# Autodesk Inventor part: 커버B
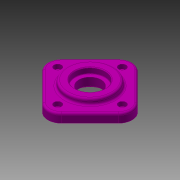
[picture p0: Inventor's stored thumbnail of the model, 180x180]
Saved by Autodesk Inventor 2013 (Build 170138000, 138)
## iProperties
Created: 2013-01
Part Number: 커버B
Document SubType Name: Modeling
Density: 1 g/cm^3
Material: 알루미늄 6061
Designer: mdu
Author: mdu
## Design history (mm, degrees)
sketch "스케치1"
  geometry: L1 (56.569, -14.142)-(14.142, -56.569) reference; L2 (-14.142, -56.569)-(-56.569, -14.142) reference; L3 (-56.569, 14.142)-(-14.142, 56.569) reference; L4 (14.142, 56.569)-(56.569, 14.142) reference; C1 r 31 at (0, 0) reference; A1 r 20 centre (0, -42.426) between (-14.142, -56.569) and (14.142, -56.569) reference; A2 r 20 centre (-42.426, 0) between (-56.569, 14.142) and (-56.569, -14.142) reference; A3 r 20 centre (0, 42.426) between (14.142, 56.569) and (-14.142, 56.569) reference; A4 r 20 centre (42.426, 0) between (56.569, -14.142) and (56.569, 14.142) reference; 1 further point
extrude "돌출1" new body sketch "스케치1" distance "d0" = 13; taper "d1" = 0 deg
sketch "스케치2"
  geometry: C1 r 35 at (0, 0); 1 further point
  constraints: 1 centre point, 1 coincident
  dimensions: "d2" = 70 diameter of C1
extrude "돌출2" join sketch "스케치2" distance "d3" = 8; taper "d4" = 0 deg
fillet "모깎기1" dims "d5" = 3
sketch "스케치3"
  geometry: C1 r 2.458 at (0, 48) reference; 1 further point
hole "구멍1" sketch "스케치3" at (0, 48) diameter "d6" = 6.6; stored, may be unused: countersink angle "d10" = 90 deg, drill point angle "d12" = 118 deg; dims "d7" = 6, "d8" = 11, "d9" = 6.5, "d11" = 8
hole "구멍2" diameter "d18" = 33; stored, may be unused: countersink angle "d22" = 90 deg, drill point angle "d24" = 118 deg; dims "d19" = 6, "d20" = 45, "d21" = 8.5, "d23" = 8, "d41" = 10, "d42" = 10
sketch "스케치4"
  geometry: C1 r 31 at (0, 0) reference; 1 further point
extrude "돌출3" join sketch "스케치4" distance "d25" = 6; taper "d26" = 0 deg
hole "구멍3" diameter "d29" = 50; stored, may be unused: countersink angle "d33" = 90 deg, drill point angle "d35" = 0 deg; dims "d27" = 10, "d28" = 10, "d30" = 6, "d31" = 42, "d32" = 8.5, "d34" = 7
fillet "모깎기2" dims "d36" = 3, "d37" = 0.4
chamfer "모따기1" distance "d38" = 1; stored, may be unused: second distance "d39" = 2, angle "d40" = 45 deg
node "솔리드1"
pattern_circular "원형 패턴1" dims angle "d14" = 360 deg
node "참조1"
node "참조2"
node "참조3"
node "참조4"
node "참조5"
node "참조6"
node "참조7"
node "참조8"
node "참조9"
node "참조10"
node "참조11"
